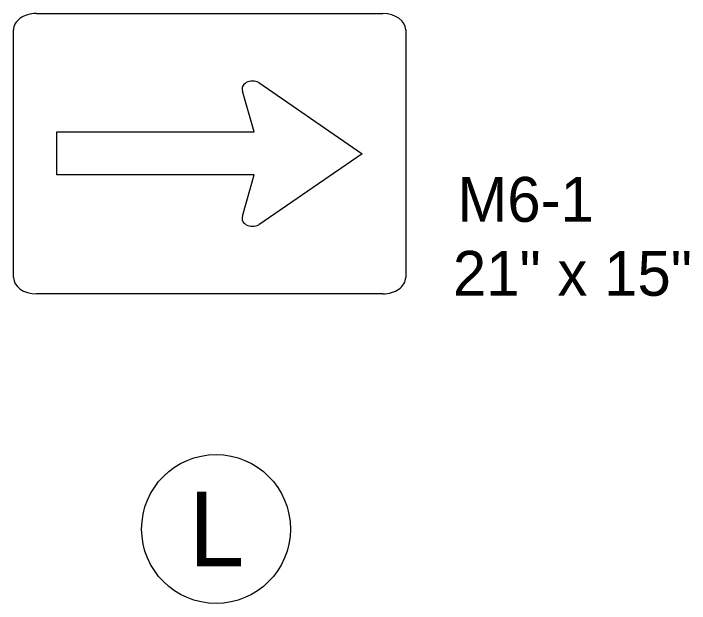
# Model space of a CAD drawing. Extents: x 2157572 to 5059327, y 715220 to 1674494.
# Drawn here: x 2166291.4 to 2166731.5, y 720621.7 to 721005.5 of the extents above; entities that cross this region are included whole.
import ezdxf

# ---------------------------------------------------------------- set-up
doc = ezdxf.new("R2010")
doc.units = 0
for name, color, linetype in [('Exist Cultural Church Label', 7, 'Continuous'), ('Level 56', 7, 'Continuous'), ('Map Preparation County Base Legend Highway Garage or Maintenance Office', 7, 'Continuous')]:
    doc.layers.add(name, color=color, linetype=linetype)

msp = doc.modelspace()

# ---------------------------------------------------------------- linework, layer by layer
at = {"layer": 'Exist Cultural Church Label'}
msp.add_circle((2166423.28, 720670.16), 48.43, dxfattribs=at)
at = {"layer": 'Level 56'}
for p, q in [((2166419.1, 721005.5), (2166419.1, 721005.5)), ((2166451.05, 720960.65), (2166518.33, 720914.32)), ((2166448.13, 720928.61), (2166440.54, 720955.01)), ((2166319.71, 720900.51), (2166319.72, 720928.61)), ((2166319.72, 720928.61), (2166448.13, 720928.61)), ((2166518.33, 720914.32), (2166451.05, 720867.98)), ((2166448.12, 720900.51), (2166319.71, 720900.51)), ((2166440.54, 720873.62), (2166448.12, 720900.51))]:
    msp.add_line(p, q, dxfattribs=at)
for points in [[(2166306.33, 721005.5), (2166531.86, 721005.5)], [(2166291.43, 720833.76), (2166291.43, 720994.86)], [(2166546.75, 720994.86), (2166546.75, 720833.77)], [(2166531.86, 720823.13), (2166306.33, 720823.13)]]:
    msp.add_lwpolyline(points, dxfattribs=at)
for centre, major_axis, ratio, start_param, end_param in [((2166306.33, 720994.86), (-14.89, 0), 0.714286, 4.712162, 6.283185), ((2166531.86, 720994.86), (14.89, 0), 0.714286, 0, 1.570796), ((2166447.14, 720956.54), (6.93, 0), 0.720018, 0.96961, 3.452569), ((2166447.14, 720872.09), (6.93, 0), 0.720018, 2.830617, 5.313577), ((2166306.33, 720833.77), (-14.89, 0), 0.714286, 0, 1.570796), ((2166531.86, 720833.77), (-14.89, 0), 0.714286, 1.570796, 3.141593)]:
    msp.add_ellipse(centre, major_axis=major_axis, ratio=ratio, start_param=start_param, end_param=end_param, dxfattribs=at)
at = {"layer": 'Map Preparation County Base Legend Highway Garage or Maintenance Office'}
msp.add_circle((2166423.28, 720670.16), 48.43, dxfattribs=at)

# ---------------------------------------------------------------- texts
at = {"layer": 'Exist Cultural Church Label'}
msp.add_text('L', height=48.63, dxfattribs=at).set_placement((2166405.6, 720645.84))
at = {"layer": 'Level 56'}
for s, p in [('M6-1', (2166580.42, 720870)), ('21" x 15"', (2166577.49, 720821.91))]:
    msp.add_text(s, height=29.18, rotation=360, dxfattribs=at).set_placement(p)

doc.saveas('drawing.dxf')
